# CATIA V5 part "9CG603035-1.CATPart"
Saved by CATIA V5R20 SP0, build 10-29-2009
Part number: 9CG603035-1
Revision: ANY
Definition: UNKNOWN
Nomenclature: 9CG603035-1
Source: Unknown
Bounding box of the stored display mesh (mm): x -25 to 35, y -18 to 23, z -15 to 15
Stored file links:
  C:\Users\Utente\Desktop\IO LAVORO\3D X SITO CF\CUMSA\3D files CG\CG 603035\9CG603035-1.CATPart
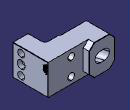
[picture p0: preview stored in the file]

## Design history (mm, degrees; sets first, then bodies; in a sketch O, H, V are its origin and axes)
Body1 "Envolver1" (main body)
  Solid1: solid without history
